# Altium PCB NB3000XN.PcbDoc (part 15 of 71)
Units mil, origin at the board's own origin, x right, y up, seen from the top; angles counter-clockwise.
Board outline 9527.56 x 6929.77 mil, 6 copper layers (Top Layer, GND+SHIELD, MidLayer1, MidLayer2, P2 - 3V3+5V0, Bottom Layer), stack 62.375 mil thick; 832 components, 1027 nets, 4655 pads, 4981 vias.
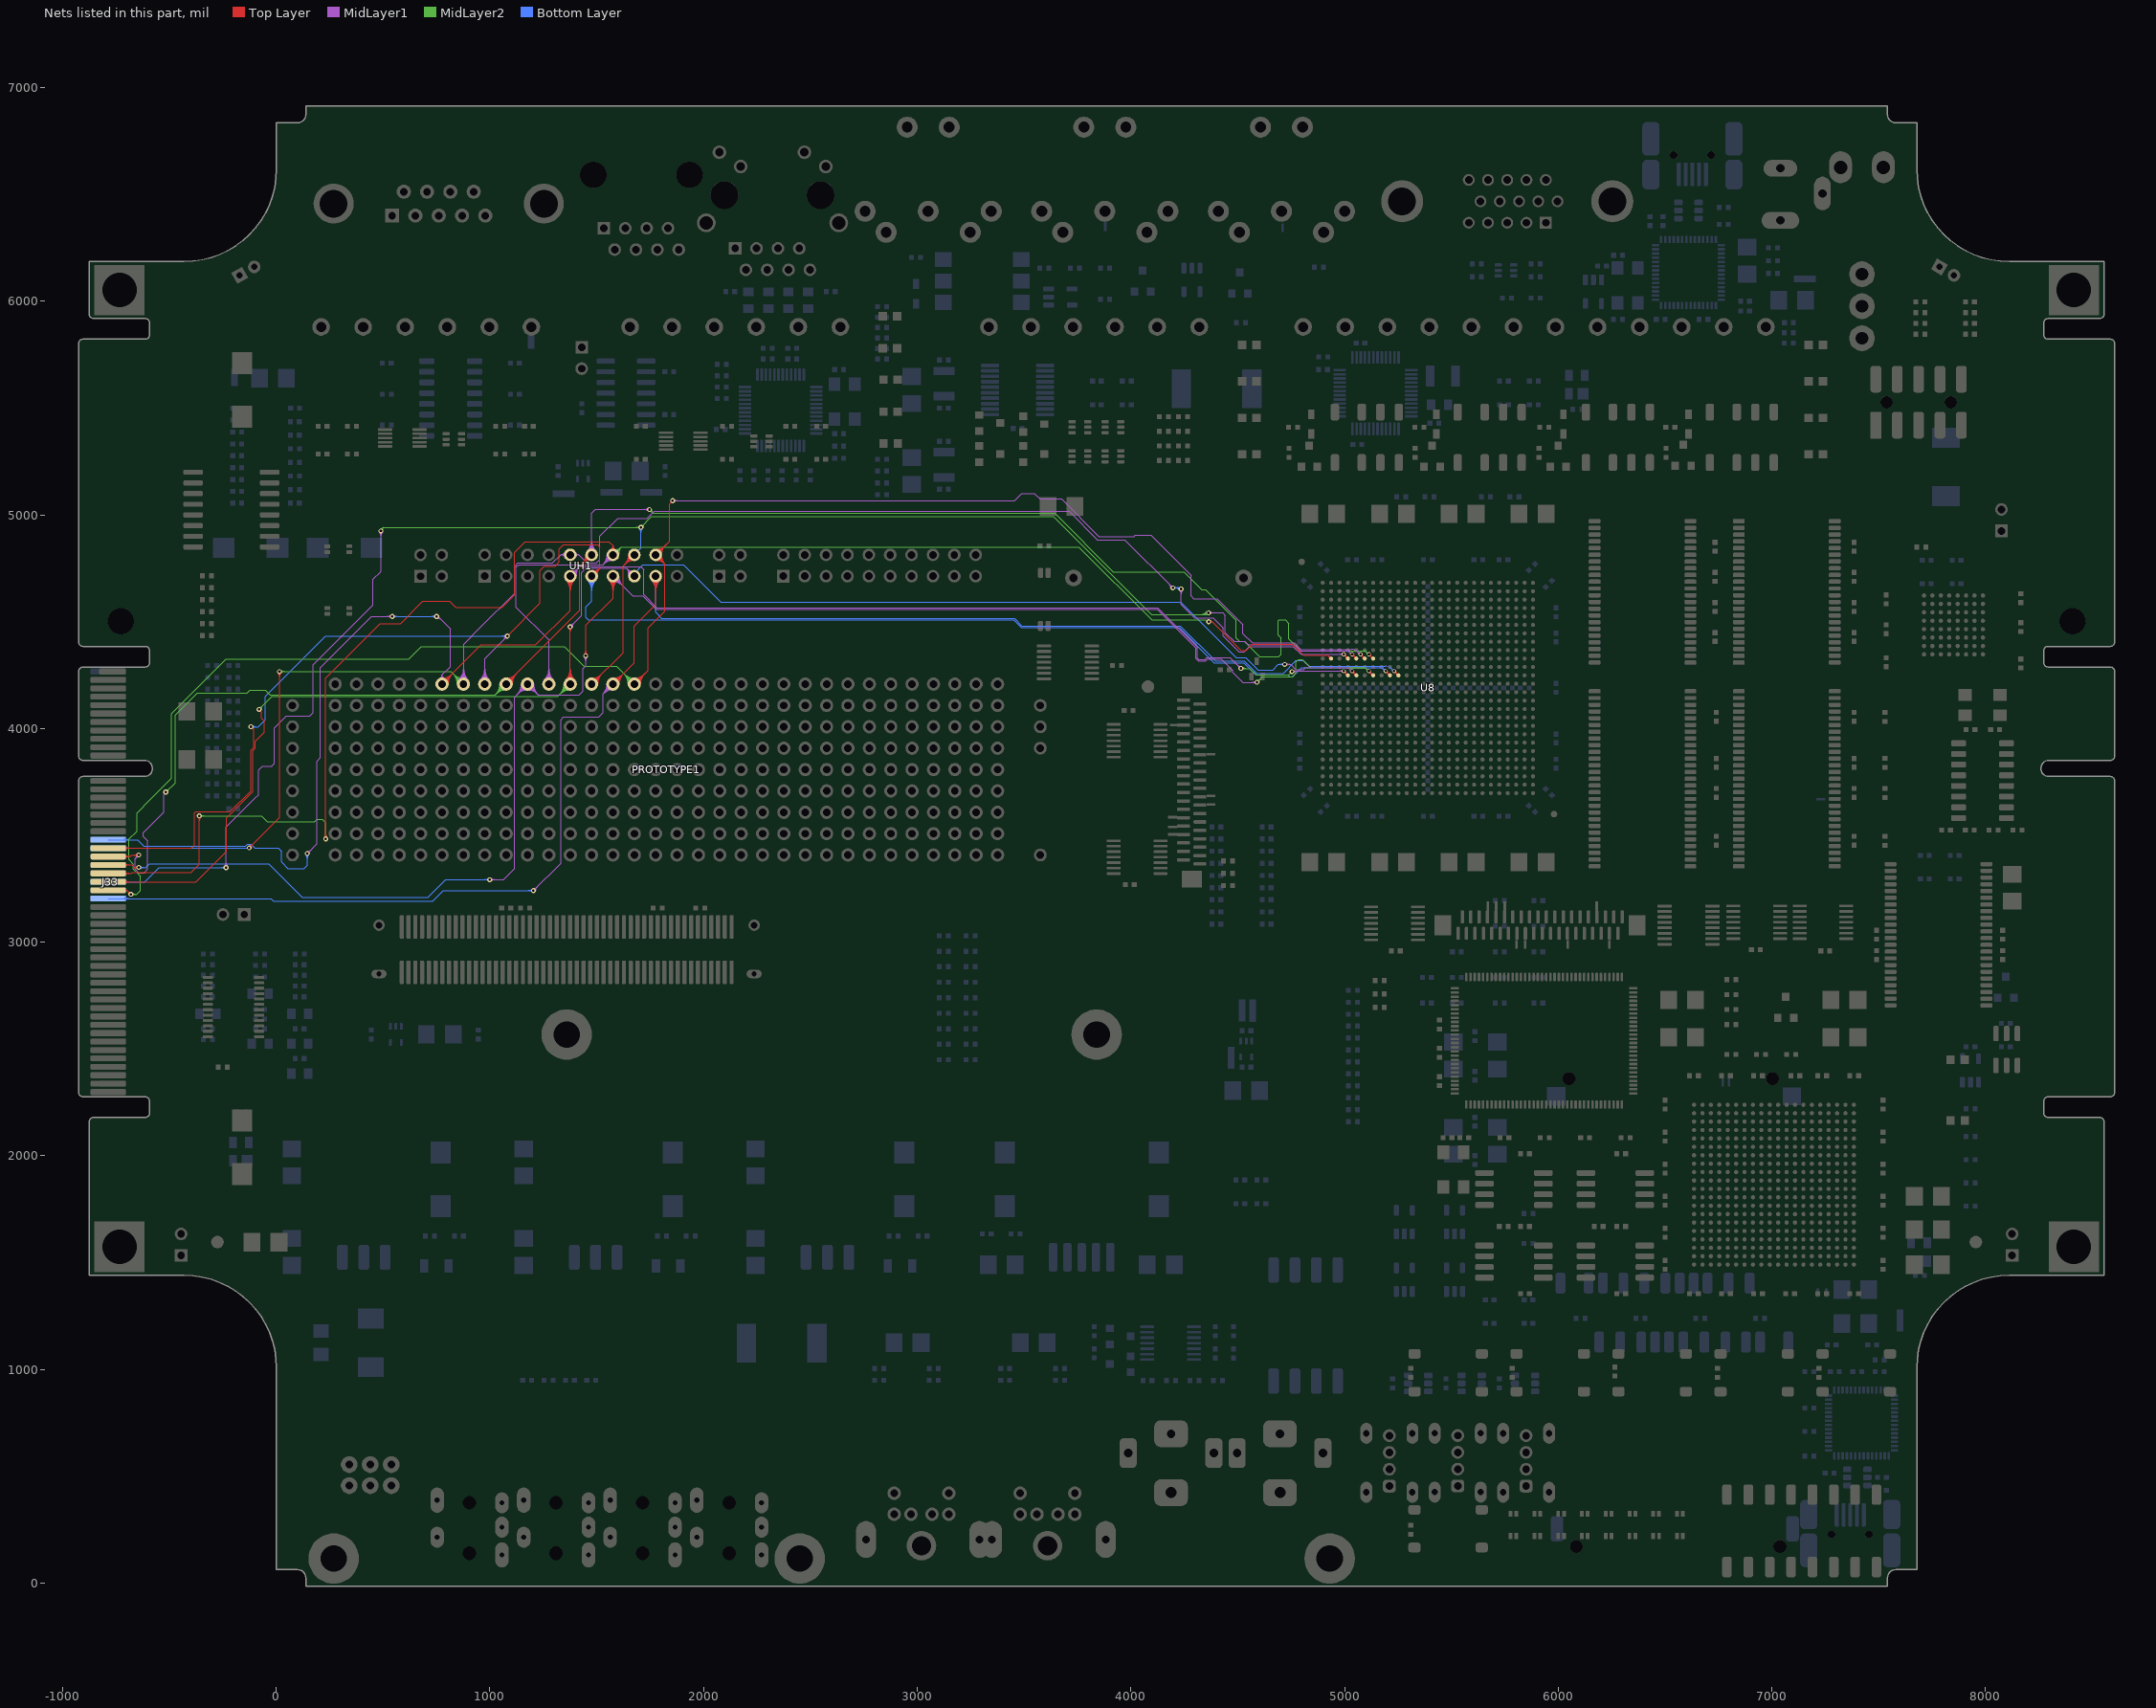
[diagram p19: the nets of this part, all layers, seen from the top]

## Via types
v1: diameter 23, hole 11.81, Top Layer to Bottom Layer, 3672 vias
v2: diameter 26, hole 11.81, Top Layer to Bottom Layer, 461 vias
v3: diameter 19, hole 11.81, Top Layer to Bottom Layer, tented both sides, 396 vias
v4: diameter 23.62, hole 11.81, Top Layer to Bottom Layer, 288 vias
v5: diameter 20, hole 11.81, Top Layer to Bottom Layer, 91 vias
v6: diameter 23, hole 11.81, Top Layer to Bottom Layer, tented both sides, 50 vias
v7: diameter 31, hole 11.81, Top Layer to Bottom Layer, 15 vias
v8: diameter 27.56, hole 11.81, Top Layer to Bottom Layer, tented both sides, 4 vias
v9: diameter 29, hole 11.81, Top Layer to Bottom Layer, 3 vias
v10: diameter 21, hole 11.81, Top Layer to Bottom Layer, 1 vias

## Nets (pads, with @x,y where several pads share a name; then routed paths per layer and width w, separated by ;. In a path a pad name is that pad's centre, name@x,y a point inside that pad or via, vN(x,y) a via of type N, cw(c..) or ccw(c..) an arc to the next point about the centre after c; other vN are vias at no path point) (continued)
ATE.UIO.IO7: J33.B19 PROTOTYPE1.H6 U8.M4 UH1.9 | length 9710.7
  Top Layer w4: PROTOTYPE1.H6@776.12,4208.23 959.59,4391.71 1215.19,4391.71 1376.12,4552.64 UH1.9@1376.12,4713.23 ; PROTOTYPE1.H6@776.12,4221.23 ccw(c776.12,4252.62) 798.31,4230.43 ccw(c820.51,4208.23) PROTOTYPE1.H6@789.12,4208.23 ; PROTOTYPE1.H6@776.12,4225.23 ccw(c776.12,4266.28) 805.14,4237.26 ccw(c834.16,4208.23) PROTOTYPE1.H6@793.12,4208.23 ; PROTOTYPE1.H6@776.12,4229.23 ccw(c776.12,4279.93) 811.97,4244.08 ccw(c847.82,4208.23) PROTOTYPE1.H6@797.12,4208.23 ; PROTOTYPE1.H6@776.12,4233.23 ccw(c776.12,4293.59) 818.8,4250.91 ccw(c861.48,4208.23) PROTOTYPE1.H6@801.12,4208.23 ; PROTOTYPE1.H6@776.12,4237.23 ccw(c776.12,4307.25) 825.63,4257.74 ccw(c875.13,4208.23) PROTOTYPE1.H6@805.12,4208.23 ; UH1.9@1356.66,4693.77 cw(c1309.66,4646.78) 1376.12,4646.78 cw(c1442.58,4646.78) UH1.9@1395.59,4693.77 ; UH1.9@1359.48,4696.6 cw(c1319.32,4656.43) 1376.12,4656.43 cw(c1432.92,4656.43) UH1.9@1392.76,4696.6 ; UH1.9@1362.31,4699.43 cw(c1328.98,4666.09) 1376.12,4666.09 cw(c1423.26,4666.09) UH1.9@1389.93,4699.43 ; UH1.9@1365.14,4702.26 cw(c1338.63,4675.75) 1376.12,4675.75 cw(c1413.61,4675.75) UH1.9@1387.1,4702.26 ; v3(4996.3,4268.74) U8.M4@5015.98,4249.06 ; U8.M4@5008.48,4249.06 ccw(c4990.38,4249.06) 5003.18,4261.86 ccw(c5015.98,4274.66) U8.M4@5015.98,4256.56 ; U8.M4@5008.64,4249.06 ccw(c4990.92,4249.06) 5003.45,4261.59 ccw(c5015.98,4274.12) U8.M4@5015.98,4256.4 ; 5009.1,4255.94 cw(c5021.91,4268.74) 5003.8,4268.74 ccw(c5021.91,4268.74) 5009.1,4255.94 ; 5009.1,4255.94 ccw(c4996.3,4243.13) 4996.3,4261.24 cw(c4996.3,4243.13) 5009.1,4255.94
  MidLayer1 w4: v1(145,3415) 190,3460 190,3846.87 206.19,3863.06 206.19,4285.08 446.15,4525.04 v1(542.86,4525.04) ; v1@145,3420.5 ccw(c145,3433.78) 154.39,3424.39 ccw(c163.78,3415) v1@150.5,3415 ; v1@145,3424.5 ccw(c145,3447.43) 161.22,3431.22 ccw(c177.43,3415) v1@154.5,3415 ; v1@536.14,4518.32 ccw(c519.92,4502.11) 519.92,4525.04 ccw(c519.92,4547.98) v1@536.14,4531.76 ; v1@538.97,4521.15 ccw(c529.58,4511.76) 529.58,4525.04 ccw(c529.58,4538.32) v1@538.97,4528.93 ; v1@750.86,4515.54 cw(c750.86,4478.92) 776.75,4504.82 ; v1@750.86,4519.54 cw(c750.86,4492.58) 769.92,4511.64 ; v1@750.86,4523.54 cw(c750.86,4506.24) 763.09,4518.47 cw(c769.61,4525.04) v1@760.36,4525.04 ; v1@756.52,4525.04 815.37,4466.19 815.37,4289.87 776.12,4250.62 ; PROTOTYPE1.H6@765.62,4235.27 ccw(c759.65,4250.62) 776.12,4250.62 ; PROTOTYPE1.H6@767.07,4231.54 ccw(c761.92,4244.77) 776.12,4244.77 ccw(c790.32,4244.77) PROTOTYPE1.H6@785.18,4231.54 ; PROTOTYPE1.H6@776.12,4208.23 776.12,4250.62 ; PROTOTYPE1.H6@786.63,4235.27 cw(c792.59,4250.62) 776.12,4250.62 ; UH1.9@1376.12,4713.23 1421.26,4758.37 ; UH1.9@1376.57,4728.76 ccw(c1377.55,4762.73) 1401.58,4738.7 ccw(c1425.61,4714.66) UH1.9@1391.64,4713.68 ; UH1.9@1376.69,4732.75 ccw(c1377.92,4775.48) 1408.14,4745.25 ccw(c1438.36,4715.03) UH1.9@1395.64,4713.8 ; UH1.9@1376.8,4736.75 ccw(c1378.29,4788.22) 1414.7,4751.81 ccw(c1451.11,4715.4) UH1.9@1399.64,4713.91 ; UH1.9@1376.92,4740.75 ccw(c1378.66,4800.97) 1421.26,4758.37 ; UH1.9@1403.64,4714.03 cw(c1463.86,4715.77) 1421.26,4758.37 ; v1@4505.69,4281.71 ccw(c4482.76,4281.71) 4498.97,4297.93 ccw(c4515.19,4314.14) v1@4515.19,4291.21 ; v1@4509.69,4281.71 ccw(c4496.41,4281.71) 4505.8,4291.1 ccw(c4515.19,4300.49) v1@4515.19,4287.21 ; v1(4515.19,4281.71) 4464.36,4332.54 4354.91,4332.54 4346.58,4324.21 4318.31,4324.21 4311.6,4330.92 4311.6,4380.77 4126.33,4566.04 1781.59,4566.04 1720,4627.63 1720,4745 1706.63,4758.37 1421.26,4758.37 ; v1(4754.19,4266.71) 4770.19,4266.71 ; v1@4762.53,4262.16 cw(c4770.19,4257.98) 4770.19,4266.71 ; v1@4762.53,4271.26 ccw(c4770.19,4275.43) 4770.19,4266.71 ; v3@4991,4263.44 ccw(c4978.19,4250.63) 4978.19,4268.74 ccw(c4978.19,4286.85) v3@4991,4274.04 ; v3@4991.11,4263.55 ccw(c4978.57,4251.01) 4978.57,4268.74 ccw(c4978.57,4286.47) v3@4991.11,4273.93 ; v3(4996.3,4268.74) 4918.62,4268.74 4870,4268.74 4860,4268.74 4855.26,4268.74 4772.22,4268.74 4770.19,4266.71
  MidLayer2 w4: v1(4515.19,4281.71) 4555.54,4281.71 4586.21,4251.04 4738.52,4251.04 v1(4754.19,4266.71) ; v1@4519.08,4277.82 cw(c4528.47,4268.43) 4528.47,4281.71 cw(c4528.47,4294.99) v1@4519.08,4285.6 ; v1@4521.91,4274.99 cw(c4538.13,4258.77) 4538.13,4281.71 cw(c4538.13,4304.64) v1@4521.91,4288.43
  Bottom Layer w4: J33.B19@-785.98,3479.63 -649.38,3479.63 -619.75,3450 -142.93,3450 -133.72,3459.21 -119.23,3459.21 -100.89,3440.87 -75.87,3440.87 9.13,3440.87 25,3425 25,3375 55,3345 130,3345 145,3360 v1(145,3415) ; J33.B19@-711.58,3474.13 cw(c-698.3,3460.85) -698.3,3479.63 cw(c-698.3,3498.41) J33.B19@-711.58,3485.13 ; J33.B19@-708.76,3471.3 cw(c-688.65,3451.19) -688.65,3479.63 cw(c-688.65,3508.07) J33.B19@-708.76,3487.96 ; v1@138.28,3408.28 cw(c122.06,3392.06) 145,3392.06 cw(c167.93,3392.06) v1@151.72,3408.28 ; v1@141.11,3411.11 cw(c131.72,3401.72) 145,3401.72 cw(c158.28,3401.72) v1@148.89,3411.11 ; v1(542.86,4525.04) v1(750.86,4525.04) ; v1@546.75,4521.15 cw(c556.14,4511.76) 556.14,4525.04 cw(c556.14,4538.32) v1@546.75,4528.93 ; v1@549.57,4518.32 cw(c565.79,4502.11) 565.79,4525.04 cw(c565.79,4547.98) v1@549.57,4531.76 ; v1@744.14,4518.32 ccw(c727.92,4502.11) 727.92,4525.04 ccw(c727.92,4547.98) v1@744.14,4531.76 ; v1@746.97,4521.15 ccw(c737.58,4511.76) 737.58,4525.04 ccw(c737.58,4538.32) v1@746.97,4528.93
ATE.UIO.IO8: J33.B20 PROTOTYPE1.H7 U8.K4 UH1.10 | length 9204.3
  Top Layer w4: v1(-126.48,3441.71) 15.19,3583.37 15.19,4228.33 v1(15.19,4266.71) ; v1@-126.48,3447.21 ccw(c-126.48,3460.49) -117.09,3451.1 ccw(c-107.7,3441.71) v1@-120.98,3441.71 ; v1@-126.48,3451.21 ccw(c-126.48,3474.14) -110.26,3457.93 ccw(c-94.04,3441.71) v1@-116.98,3441.71 ; v1@8.47,4259.99 cw(c-7.74,4243.77) 15.19,4243.77 cw(c38.13,4243.77) v1@21.91,4259.99 ; v1@11.3,4262.82 cw(c1.91,4253.43) 15.19,4253.43 cw(c28.47,4253.43) v1@19.08,4262.82 ; v3(4996.3,4347.48) U8.K4@5015.98,4327.8 ; U8.K4@5008.48,4327.8 ccw(c4990.38,4327.8) 5003.18,4340.6 ccw(c5015.98,4353.4) U8.K4@5015.98,4335.3 ; U8.K4@5008.64,4327.8 ccw(c4990.92,4327.8) 5003.45,4340.33 ccw(c5015.98,4352.86) U8.K4@5015.98,4335.14 ; 5009.1,4334.68 cw(c5021.91,4347.48) 5003.8,4347.48 ccw(c5021.91,4347.48) 5009.1,4334.68 ; 5009.1,4334.68 ccw(c4996.3,4321.87) 4996.3,4339.98 cw(c4996.3,4321.87) 5009.1,4334.68
  MidLayer1 w4: PROTOTYPE1.H7@855.62,4228.74 ccw(c802.78,4281.58) 877.5,4281.58 ; PROTOTYPE1.H7@858.44,4225.91 ccw(c812.44,4271.92) 877.5,4271.92 ; PROTOTYPE1.H7@861.27,4223.08 ccw(c822.09,4262.26) 877.5,4262.26 ; PROTOTYPE1.H7@864.1,4220.26 ccw(c831.75,4252.6) 877.5,4252.6 ; PROTOTYPE1.H7@866.93,4217.43 ccw(c841.41,4242.95) 877.5,4242.95 ; PROTOTYPE1.H7@876.12,4208.23 876.12,4210 877.5,4211.38 877.5,4395.68 956.86,4475.04 1115.19,4633.37 1115.19,4758.37 1131.86,4775.04 1293.66,4775.04 1331.86,4813.23 ; 877.5,4245.95 ccw(c913.83,4245.95) PROTOTYPE1.H7@888.14,4220.26 ; 877.5,4255.6 ccw(c923.49,4255.6) PROTOTYPE1.H7@890.97,4223.08 ; 877.5,4265.26 ccw(c933.15,4265.26) PROTOTYPE1.H7@893.8,4225.91 ; 877.5,4274.92 ccw(c942.8,4274.92) PROTOTYPE1.H7@896.63,4228.74 ; UH1.10@1351.43,4801.06 ccw(c1331.86,4791.41) 1331.86,4813.23 ; UH1.10@1351.43,4825.41 cw(c1331.86,4835.06) 1331.86,4813.23 ; UH1.10@1355.02,4802.83 ccw(c1338.29,4794.58) 1338.29,4813.23 ccw(c1338.29,4831.89) UH1.10@1355.02,4823.64 ; UH1.10@1358.61,4804.6 ccw(c1344.72,4797.76) 1344.72,4813.23 ccw(c1344.72,4828.71) UH1.10@1358.61,4821.87 ; UH1.10@1398.28,4805.32 cw(c1409.51,4801.3) 1409.51,4813.23 cw(c1409.51,4825.17) UH1.10@1398.28,4821.15 ; UH1.10@1402.04,4803.97 cw(c1415.19,4799.28) 1415.19,4813.23 ; UH1.10@1402.04,4822.5 ccw(c1415.19,4827.19) 1415.19,4813.23 ; v1@4187.02,4658.37 ccw(c4164.09,4658.37) 4180.31,4674.59 ccw(c4196.52,4690.81) v1@4196.52,4667.87 ; v1@4191.02,4658.37 ccw(c4177.75,4658.37) 4187.14,4667.76 ccw(c4196.52,4677.15) v1@4196.52,4663.87 ; v1(4196.52,4658.37) 3971.52,4883.37 3844,4883.37 3710.33,5017.04 1768.67,5017.04 1735,4983.37 1598.52,4983.37 1515.19,4900.04 1515.19,4791.71 1498.52,4775.04 1453.38,4775.04 1415.19,4813.23 ; v1@4228.81,4646.66 cw(c4212.59,4630.44) 4235.52,4630.44 cw(c4258.46,4630.44) v1@4242.24,4646.66 ; v1@4231.64,4649.49 cw(c4222.25,4640.1) 4235.52,4640.1 cw(c4248.8,4640.1) v1@4239.41,4649.49 ; v1(4235.52,4653.37) 4235.52,4579.71 4297.52,4517.71 4385.15,4517.71 4432.86,4470 4432.86,4434.04 4506.9,4360 4530,4360 4554.71,4384.71 4760,4384.71 4797.23,4347.48 4810.14,4347.48 4860,4347.48 4870,4347.48 4918.62,4347.48 v3(4996.3,4347.48) ; v3@4991.11,4342.29 ccw(c4978.57,4329.75) 4978.57,4347.48 ccw(c4978.57,4365.21) v3@4991.11,4352.67 ; 1331.86,4813.23 UH1.10@1376.12,4813.23 1415.19,4813.23 ; 4978.19,4347.48 cw(c4978.19,4329.37) 4991,4342.18 ccw(c4978.19,4329.37) 4978.19,4347.48 ; 4978.19,4347.48 ccw(c4978.19,4365.59) 4991,4352.78 cw(c4978.19,4365.59) 4978.19,4347.48
  MidLayer2 w4: v1(15.19,4266.71) 817.65,4266.71 PROTOTYPE1.H7@876.12,4208.23 ; v1@19.08,4262.82 cw(c28.47,4253.43) 28.47,4266.71 cw(c28.47,4279.99) v1@19.08,4270.6 ; v1@21.91,4259.99 cw(c38.13,4243.77) 38.13,4266.71 cw(c38.13,4289.64) v1@21.91,4273.43 ; PROTOTYPE1.H7@847.12,4208.23 ccw(c777.11,4208.23) 826.62,4257.74 ccw(c876.12,4307.25) PROTOTYPE1.H7@876.12,4237.23 ; PROTOTYPE1.H7@851.12,4208.23 ccw(c790.77,4208.23) 833.44,4250.91 ccw(c876.12,4293.59) PROTOTYPE1.H7@876.12,4233.23 ; PROTOTYPE1.H7@855.12,4208.23 ccw(c804.42,4208.23) 840.27,4244.08 ccw(c876.12,4279.93) PROTOTYPE1.H7@876.12,4229.23 ; PROTOTYPE1.H7@859.12,4208.23 ccw(c818.08,4208.23) 847.1,4237.26 ccw(c876.12,4266.28) PROTOTYPE1.H7@876.12,4225.23 ; PROTOTYPE1.H7@863.12,4208.23 ccw(c831.74,4208.23) 853.93,4230.43 ccw(c876.12,4252.62) PROTOTYPE1.H7@876.12,4221.23
  Bottom Layer w4: J33.B20@-785.98,3440.26 -155,3440.26 -153.56,3441.71 v1(-126.48,3441.71) ; J33.B20@-711.58,3434.76 cw(c-698.3,3421.48) -698.3,3440.26 cw(c-698.3,3459.04) J33.B20@-711.58,3445.76 ; J33.B20@-708.76,3431.93 cw(c-688.65,3411.82) -688.65,3440.26 cw(c-688.65,3468.7) J33.B20@-708.76,3448.59 ; v1(4196.52,4658.37) 4230.52,4658.37 v1(4235.52,4653.37) ; v1@4200.41,4654.49 cw(c4209.8,4645.1) 4209.8,4658.37 cw(c4209.8,4671.65) v1@4200.41,4662.26 ; v1@4200.52,4658.37 cw(c4200.52,4618.37) v1@4228.81,4646.66 ; v1@4203.24,4651.66 cw(c4219.46,4635.44) 4219.46,4658.37 cw(c4219.46,4681.31) v1@4203.24,4665.09 ; 4210.17,4658.37 cw(c4210.17,4628.03) v1@4231.64,4649.49 ; 4219.83,4658.37 cw(c4219.83,4637.68) v1@4234.46,4652.31 ; 4224.66,4658.37 ccw(c4224.66,4664.24) v1@4228.81,4660.09
ATE.UIO.IO9: J33.A20 PROTOTYPE1.H8 U8.M9 UH1.11 | length 9283.3
  Top Layer w4: J33.A20@-785.98,3440.26 -394.74,3440.26 -381.5,3453.5 -381.5,3605 -376.5,3610 -216.31,3610 -118,3708.31 -118,3898.31 -105,3911.31 -105,3995.23 v1(-118.14,4008.37) ; J33.A20@-711.58,3434.76 cw(c-698.3,3421.48) -698.3,3440.26 cw(c-698.3,3459.04) J33.A20@-711.58,3445.76 ; J33.A20@-708.76,3431.93 cw(c-688.65,3411.82) -688.65,3440.26 cw(c-688.65,3468.7) J33.A20@-708.76,3448.59 ; v1(1081.52,4433.04) 1235,4586.52 1235,4740 1255,4760 1305,4760 1325,4780 1325,4840 1345,4860 1505,4860 1515.19,4849.81 1515.19,4752.3 ; v1@1081.52,4438.54 ccw(c1081.52,4451.82) 1090.91,4442.43 ccw(c1100.3,4433.04) v1@1087.02,4433.04 ; v1@1081.52,4442.54 ccw(c1081.52,4465.48) 1097.74,4449.26 ccw(c1113.96,4433.04) v1@1091.02,4433.04 ; UH1.11@1476.12,4713.23 1515.19,4752.3 ; UH1.11@1478.27,4728.61 ccw(c1481.53,4751.9) 1498.16,4735.27 ccw(c1514.78,4718.65) UH1.11@1491.5,4715.39 ; UH1.11@1478.83,4732.57 ccw(c1482.93,4761.85) 1503.83,4740.95 ccw(c1524.74,4720.04) UH1.11@1495.46,4715.94 ; UH1.11@1479.38,4736.54 ccw(c1484.32,4771.81) 1509.51,4746.62 ccw(c1534.7,4721.44) UH1.11@1499.42,4716.5 ; UH1.11@1479.94,4740.5 ccw(c1485.72,4781.77) 1515.19,4752.3 ; UH1.11@1503.38,4717.05 cw(c1544.66,4722.83) 1515.19,4752.3 ; v3(5193.15,4268.74) U8.M9@5212.83,4249.06 ; U8.M9@5205.33,4249.06 ccw(c5187.23,4249.06) 5200.03,4261.86 ccw(c5212.83,4274.66) U8.M9@5212.83,4256.56 ; U8.M9@5205.49,4249.06 ccw(c5187.77,4249.06) 5200.3,4261.59 ccw(c5212.83,4274.12) U8.M9@5212.83,4256.4 ; 5205.95,4255.94 ccw(c5193.15,4243.13) 5193.15,4261.24 cw(c5193.15,4243.13) 5205.95,4255.94 ; 5205.95,4255.94 cw(c5218.76,4268.74) 5200.65,4268.74 ccw(c5218.76,4268.74) 5205.95,4255.94
  MidLayer1 w4: PROTOTYPE1.H8@955.62,4228.74 ccw(c906.11,4278.25) 976.12,4278.25 ccw(c1046.13,4278.25) PROTOTYPE1.H8@996.63,4228.74 ; PROTOTYPE1.H8@958.44,4225.91 ccw(c915.77,4268.59) 976.12,4268.59 ccw(c1036.48,4268.59) PROTOTYPE1.H8@993.8,4225.91 ; PROTOTYPE1.H8@961.27,4223.08 ccw(c925.42,4258.93) 976.12,4258.93 ccw(c1026.82,4258.93) PROTOTYPE1.H8@990.97,4223.08 ; PROTOTYPE1.H8@964.1,4220.26 ccw(c935.08,4249.28) 976.12,4249.28 ccw(c1017.16,4249.28) PROTOTYPE1.H8@988.14,4220.26 ; PROTOTYPE1.H8@966.93,4217.43 ccw(c944.74,4239.62) 976.12,4239.62 ccw(c1007.51,4239.62) PROTOTYPE1.H8@985.31,4217.43 ; PROTOTYPE1.H8@976.12,4208.23 976.12,4327.64 v1(1081.52,4433.04) ; v1@1072.02,4433.04 cw(c1049.09,4433.04) 1065.31,4416.82 cw(c1081.52,4400.61) v1@1081.52,4423.54 ; v1@1076.02,4433.04 cw(c1062.75,4433.04) 1072.14,4423.65 cw(c1081.52,4414.26) v1@1081.52,4427.54
  Bottom Layer w4: v1(-118.14,4008.37) -84.81,4008.37 -51.48,4041.71 -51.48,4150.04 231.52,4433.04 v1(1081.52,4433.04) ; v1@-114.25,4004.49 cw(c-104.86,3995.1) -104.86,4008.37 cw(c-104.86,4021.65) v1@-114.25,4012.26 ; v1@-111.43,4001.66 cw(c-95.21,3985.44) -95.21,4008.37 cw(c-95.21,4031.31) v1@-111.43,4015.09 ; v1@1074.81,4426.32 ccw(c1058.59,4410.11) 1058.59,4433.04 ccw(c1058.59,4455.98) v1@1074.81,4439.76 ; v1@1077.64,4429.15 ccw(c1068.25,4419.76) 1068.25,4433.04 ccw(c1068.25,4446.32) v1@1077.64,4436.93 ; UH1.11@1456.66,4693.77 cw(c1409.66,4646.78) 1476.12,4646.78 cw(c1542.58,4646.78) UH1.11@1495.59,4693.77 ; UH1.11@1459.48,4696.6 cw(c1419.32,4656.43) 1476.12,4656.43 cw(c1532.92,4656.43) UH1.11@1492.76,4696.6 ; UH1.11@1462.31,4699.43 cw(c1428.98,4666.09) 1476.12,4666.09 cw(c1523.26,4666.09) UH1.11@1489.93,4699.43 ; UH1.11@1465.14,4702.26 cw(c1438.63,4675.75) 1476.12,4675.75 cw(c1513.61,4675.75) UH1.11@1487.1,4702.26 ; UH1.11@1476.12,4713.23 1476.12,4596.12 1450,4570 1450,4520 1461.63,4508.37 3451.5,4508.37 3486.88,4473 4225.56,4473 4390.19,4308.37 4528.19,4308.37 4585.52,4251.04 4733.86,4251.04 4743.19,4241.71 4757.65,4241.71 4800.19,4284.25 4855.26,4284.25 4860,4284.25 4870,4284.25 5076.1,4284.25 5169.64,4284.25 cw(c5169.64,4270.2) 5179.57,4280.13 ; v3@5185.68,4268.09 ccw(c5167.64,4266.51) 5179.28,4280.38 ccw(c5190.92,4294.25) v3@5192.5,4276.21
ATE.UIO.IO10: J33.A21 PROTOTYPE1.H9 U8.K7 UH1.12 | length 9907.1
  Top Layer w4: J33.A21@-785.98,3400.89 -685,3400.89 -677.52,3408.37 v1(-643.14,3408.37) ; J33.A21@-711.58,3395.39 cw(c-698.3,3382.11) -698.3,3400.89 cw(c-698.3,3419.67) J33.A21@-711.58,3406.39 ; J33.A21@-708.76,3392.56 cw(c-688.65,3372.45) -688.65,3400.89 cw(c-688.65,3429.33) J33.A21@-708.76,3409.22 ; v1@-649.86,3401.66 ccw(c-666.08,3385.44) -666.08,3408.37 ccw(c-666.08,3431.31) v1@-649.86,3415.09 ; v1@-647.03,3404.49 ccw(c-656.42,3395.1) -656.42,3408.37 ccw(c-656.42,3421.65) v1@-647.03,3412.26 ; PROTOTYPE1.H9@1076.12,4208.23 1420.73,4552.84 1420.73,4757.84 UH1.12@1476.12,4813.23 ; PROTOTYPE1.H9@1076.12,4221.23 ccw(c1076.12,4252.62) 1098.31,4230.43 ccw(c1120.51,4208.23) PROTOTYPE1.H9@1089.12,4208.23 ; PROTOTYPE1.H9@1076.12,4225.23 ccw(c1076.12,4266.28) 1105.14,4237.26 ccw(c1134.16,4208.23) PROTOTYPE1.H9@1093.12,4208.23 ; PROTOTYPE1.H9@1076.12,4229.23 ccw(c1076.12,4279.93) 1111.97,4244.08 ccw(c1147.82,4208.23) PROTOTYPE1.H9@1097.12,4208.23 ; PROTOTYPE1.H9@1076.12,4233.23 ccw(c1076.12,4293.59) 1118.8,4250.91 ccw(c1161.48,4208.23) PROTOTYPE1.H9@1101.12,4208.23 ; PROTOTYPE1.H9@1076.12,4237.23 ccw(c1076.12,4307.25) 1125.63,4257.74 ccw(c1175.13,4208.23) PROTOTYPE1.H9@1105.12,4208.23 ; UH1.12@1448.59,4813.23 cw(c1382.14,4813.23) 1429.13,4766.24 cw(c1476.12,4719.25) UH1.12@1476.12,4785.71 ; UH1.12@1452.59,4813.23 cw(c1395.79,4813.23) 1435.96,4773.07 cw(c1476.12,4732.91) UH1.12@1476.12,4789.71 ; UH1.12@1456.59,4813.23 cw(c1409.45,4813.23) 1442.79,4779.9 cw(c1476.12,4746.56) UH1.12@1476.12,4793.71 ; UH1.12@1460.59,4813.23 cw(c1423.11,4813.23) 1449.61,4786.73 cw(c1476.12,4760.22) UH1.12@1476.12,4797.71 ; v3(5114.41,4347.48) U8.K7@5134.09,4327.8 ; U8.K7@5126.59,4327.8 ccw(c5108.49,4327.8) 5121.29,4340.6 ccw(c5134.09,4353.4) U8.K7@5134.09,4335.3 ; U8.K7@5126.75,4327.8 ccw(c5109.03,4327.8) 5121.56,4340.33 ccw(c5134.09,4352.86) U8.K7@5134.09,4335.14 ; 5127.21,4334.68 ccw(c5114.41,4321.87) 5114.41,4339.98 cw(c5114.41,4321.87) 5127.21,4334.68 ; 5127.21,4334.68 cw(c5140.02,4347.48) 5121.91,4347.48 ccw(c5140.02,4347.48) 5127.21,4334.68
  MidLayer1 w4: v1@-652.64,3408.37 cw(c-675.58,3408.37) -659.36,3392.16 cw(c-643.14,3375.94) v1@-643.14,3398.87 ; v1@-648.64,3408.37 cw(c-661.92,3408.37) -652.53,3398.99 cw(c-643.14,3389.6) v1@-643.14,3402.87 ; v1(-643.14,3408.37) -661.14,3390.37 -661.14,3341.71 -644.48,3325.04 -618.14,3325.04 -601.48,3341.71 -601.48,3473.71 -621.41,3493.64 -621.41,3513.59 -526.48,3608.52 -526.48,3693.04 v1(-516.81,3702.71) ; UH1.12@1456.66,4832.7 ccw(c1409.66,4879.69) 1476.12,4879.69 ccw(c1542.58,4879.69) UH1.12@1495.59,4832.7 ; UH1.12@1459.48,4829.87 ccw(c1419.32,4870.04) 1476.12,4870.04 ccw(c1532.92,4870.04) UH1.12@1492.76,4829.87 ; UH1.12@1462.31,4827.04 ccw(c1428.98,4860.38) 1476.12,4860.38 ccw(c1523.26,4860.38) UH1.12@1489.93,4827.04 ; UH1.12@1465.14,4824.21 ccw(c1438.63,4850.72) 1476.12,4850.72 ccw(c1513.61,4850.72) UH1.12@1487.1,4824.21 ; UH1.12@1476.12,4813.23 1476.12,5008.37 1493.12,5025.37 v1(1746.86,5025.37) ; v1@1740.14,5018.66 ccw(c1723.92,5002.44) 1723.92,5025.37 ccw(c1723.92,5048.31) v1@1740.14,5032.09 ; v1@1742.97,5021.49 ccw(c1733.58,5012.1) 1733.58,5025.37 ccw(c1733.58,5038.65) v1@1742.97,5029.26
  MidLayer2 w4: v1(-516.81,3702.71) -473,3746.52 -473,4063.71 -370,4166.71 -135,4166.71 -121.71,4180 -50,4180 -28.04,4158.04 1025.93,4158.04 PROTOTYPE1.H9@1076.12,4208.23 ; v1@-516.81,3708.21 ccw(c-516.81,3721.49) -507.42,3712.1 ccw(c-498.03,3702.71) v1@-511.31,3702.71 ; v1@-516.81,3712.21 ccw(c-516.81,3735.14) -500.59,3718.93 ccw(c-484.37,3702.71) v1@-507.31,3702.71 ; PROTOTYPE1.H9@1047.12,4208.23 cw(c977.11,4208.23) 1026.62,4158.73 cw(c1076.12,4109.22) PROTOTYPE1.H9@1076.12,4179.23 ; PROTOTYPE1.H9@1051.12,4208.23 cw(c990.77,4208.23) 1033.44,4165.56 cw(c1076.12,4122.88) PROTOTYPE1.H9@1076.12,4183.23 ; PROTOTYPE1.H9@1055.12,4208.23 cw(c1004.42,4208.23) 1040.27,4172.39 cw(c1076.12,4136.54) PROTOTYPE1.H9@1076.12,4187.23 ; PROTOTYPE1.H9@1059.12,4208.23 cw(c1018.08,4208.23) 1047.1,4179.21 cw(c1076.12,4150.19) PROTOTYPE1.H9@1076.12,4191.23 ; PROTOTYPE1.H9@1063.12,4208.23 cw(c1031.74,4208.23) 1053.93,4186.04 cw(c1076.12,4163.85) PROTOTYPE1.H9@1076.12,4195.23 ; v1@1746.86,5015.87 cw(c1746.86,4992.94) 1763.07,5009.16 cw(c1779.29,5025.37) v1@1756.36,5025.37 ; v1@1746.86,5019.87 cw(c1746.86,5006.6) 1756.25,5015.99 cw(c1765.64,5025.37) v1@1752.36,5025.37 ; v1(1746.86,5025.37) 1763.86,5008.37 3643.17,5008.37 3918.17,4733.37 4247.86,4733.37 4331.19,4650.04 4348.52,4650.04 4491.86,4506.71 4491.86,4423.37 4507.86,4407.37 4531.52,4407.37 4602.52,4336.37 4692.19,4336.37 4703.52,4347.71 4703.52,4423.71 4690.19,4437.04 4690.19,4504.37 4694.19,4508.37 4723.52,4508.37 4740.19,4491.71 4740.19,4419.69 4796.89,4362.99 4855.26,4362.99 4860,4362.99 4870,4362.99 4997.36,4362.99 5090.9,4362.99 cw(c5090.9,4348.94) 5100.83,4358.87 ; v3@5106.94,4346.83 ccw(c5088.9,4345.25) 5100.54,4359.12 ccw(c5112.18,4372.99) v3@5113.76,4354.95
ATE.UIO.IO11: J33.A22 PROTOTYPE1.H10 U8.M7 UH1.13 | length 9806.1
  Top Layer w4: J33.A22@-785.98,3361.52 -675,3361.52 -663.52,3350.04 ; J33.A22@-711.58,3356.02 cw(c-698.3,3342.74) -698.3,3361.52 ; J33.A22@-711.58,3367.02 ccw(c-698.3,3380.31) -698.3,3361.52 ; J33.A22@-708.76,3353.19 cw(c-688.65,3333.09) -688.65,3361.52 cw(c-688.64,3389.96) J33.A22@-708.76,3369.85 ; v1@-650.42,3343.93 ccw(c-663.52,3332.94) -663.52,3350.04 ; v1@-650.42,3356.15 cw(c-663.52,3367.14) -663.52,3350.04 ; v1@-647.36,3346.51 ccw(c-654.94,3340.14) -654.94,3350.04 ccw(c-654.94,3359.94) v1@-647.36,3353.58 ; v1(-643.14,3350.04) -663.52,3350.04 ; v1@1441.81,4347.43 ccw(c1425.59,4363.64) 1448.52,4363.64 ccw(c1471.46,4363.64) v1@1455.24,4347.43 ; v1@1444.64,4344.6 ccw(c1435.25,4353.99) 1448.52,4353.99 ccw(c1461.8,4353.99) v1@1452.41,4344.6 ; v1(1448.52,4340.71) 1448.52,4483.37 1576.12,4610.97 UH1.13@1576.12,4713.23 ; UH1.13@1556.66,4693.77 cw(c1509.66,4646.78) 1576.12,4646.78 cw(c1642.58,4646.78) UH1.13@1595.59,4693.77 ; UH1.13@1559.48,4696.6 cw(c1519.32,4656.43) 1576.12,4656.43 cw(c1632.92,4656.43) UH1.13@1592.76,4696.6 ; UH1.13@1562.31,4699.43 cw(c1528.98,4666.09) 1576.12,4666.09 cw(c1623.26,4666.09) UH1.13@1589.93,4699.43 ; UH1.13@1565.14,4702.26 cw(c1538.63,4675.75) 1576.12,4675.75 cw(c1613.61,4675.75) UH1.13@1587.1,4702.26 ; v3(5114.41,4268.74) U8.M7@5134.09,4249.06 ; U8.M7@5126.59,4249.06 ccw(c5108.49,4249.06) 5121.29,4261.86 ccw(c5134.09,4274.66) U8.M7@5134.09,4256.56 ; U8.M7@5126.75,4249.06 ccw(c5109.03,4249.06) 5121.56,4261.59 ccw(c5134.09,4274.12) U8.M7@5134.09,4256.4 ; 5127.21,4255.94 ccw(c5114.41,4243.13) 5114.41,4261.24 cw(c5114.41,4243.13) 5127.21,4255.94 ; 5127.21,4255.94 cw(c5140.02,4268.74) 5121.91,4268.74 ccw(c5140.02,4268.74) 5127.21,4255.94
  MidLayer1 w4: v1(999.52,3292.71) 1063.21,3292.71 1115.19,3344.69 1115.19,4147.3 PROTOTYPE1.H10@1176.12,4208.23 1225.98,4158.37 1418.37,4158.37 1435,4175 1435,4281.48 1448.52,4295 v1(1448.52,4340.71) ; v1@1003.41,3288.82 cw(c1012.8,3279.43) 1012.8,3292.71 cw(c1012.8,3305.99) v1@1003.41,3296.6 ; v1@1006.24,3285.99 cw(c1022.46,3269.77) 1022.46,3292.71 cw(c1022.46,3315.64) v1@1006.24,3299.43 ; PROTOTYPE1.H10@1147.12,4208.23 cw(c1077.11,4208.23) 1126.62,4158.73 cw(c1176.12,4109.22) 1176.12,4179.23 cw(c1176.12,4109.22) 1225.63,4158.73 cw(c1275.13,4208.23) PROTOTYPE1.H10@1205.12,4208.23 ; PROTOTYPE1.H10@1151.12,4208.23 cw(c1090.77,4208.23) 1133.44,4165.56 cw(c1176.12,4122.88) 1176.12,4183.23 cw(c1176.12,4122.88) 1218.8,4165.56 cw(c1261.48,4208.23) PROTOTYPE1.H10@1201.12,4208.23 ; PROTOTYPE1.H10@1155.12,4208.23 cw(c1104.42,4208.23) 1140.27,4172.39 cw(c1176.12,4136.54) 1176.12,4187.23 cw(c1176.12,4136.54) 1211.97,4172.39 cw(c1247.82,4208.23) PROTOTYPE1.H10@1197.12,4208.23 ; PROTOTYPE1.H10@1159.12,4208.23 cw(c1118.08,4208.23) 1147.1,4179.21 cw(c1176.12,4150.19) 1176.12,4191.23 cw(c1176.12,4150.19) 1205.14,4179.21 cw(c1234.16,4208.23) PROTOTYPE1.H10@1193.12,4208.23 ; PROTOTYPE1.H10@1163.12,4208.23 cw(c1131.74,4208.23) 1153.93,4186.04 cw(c1176.12,4163.85) 1176.12,4195.23 cw(c1176.12,4163.85) 1198.31,4186.04 cw(c1220.51,4208.23) PROTOTYPE1.H10@1189.12,4208.23 ; v1@1441.81,4333.99 cw(c1425.59,4317.77) 1448.52,4317.77 cw(c1471.46,4317.77) v1@1455.24,4333.99 ; v1@1444.64,4336.82 cw(c1435.25,4327.43) 1448.52,4327.43 cw(c1461.8,4327.43) v1@1452.41,4336.82 ; UH1.13@1576.12,4685.71 cw(c1576.12,4619.25) 1623.11,4666.24 cw(c1670.11,4713.23) UH1.13@1603.65,4713.23 ; UH1.13@1576.12,4689.71 cw(c1576.12,4632.91) 1616.29,4673.07 cw(c1656.45,4713.23) UH1.13@1599.65,4713.23 ; UH1.13@1576.12,4693.71 cw(c1576.12,4646.56) 1609.46,4679.9 cw(c1642.79,4713.23) UH1.13@1595.65,4713.23 ; UH1.13@1576.12,4697.71 cw(c1576.12,4660.22) 1602.63,4686.73 cw(c1629.14,4713.23) UH1.13@1591.65,4713.23 ; UH1.13@1576.12,4713.23 1669.36,4620 1716.31,4620 1778.27,4558.04 4123.02,4558.04 4303.6,4377.45 4303.6,4327.6 4315,4316.21 4349.89,4316.21 4358.23,4324.54 4422.98,4324.54 4431.48,4316.04 4476.86,4270.66 4476.86,4263.37 4523.52,4216.71 v1(4590.19,4216.71) ; v1@4583.47,4209.99 ccw(c4567.26,4193.77) 4567.26,4216.71 ccw(c4567.26,4239.64) v1@4583.47,4223.43 ; v1@4586.3,4212.82 ccw(c4576.91,4203.43) 4576.91,4216.71 ccw(c4576.91,4229.99) v1@4586.3,4220.6
  MidLayer2 w4: v1(4590.19,4216.71) 4616.52,4243.04 4756.86,4243.04 4773.52,4259.71 4773.52,4311.04 4785.86,4323.37 4802.13,4323.37 4841.26,4284.25 4855.26,4284.25 4860,4284.25 4870,4284.25 4997.36,4284.25 5090.9,4284.25 cw(c5090.9,4270.2) 5100.83,4280.13 ; v1@4590.19,4222.21 ccw(c4590.19,4235.49) 4599.58,4226.1 ccw(c4608.97,4216.71) v1@4595.69,4216.71 ; v1@4590.19,4226.21 ccw(c4590.19,4249.14) 4606.41,4232.92 ccw(c4622.63,4216.71) v1@4599.69,4216.71 ; v3@5106.94,4268.09 ccw(c5088.9,4266.51) 5100.54,4280.38 ccw(c5112.18,4294.25) v3@5113.76,4276.21
  Bottom Layer w4: v1(-643.14,3350.04) -609.81,3350.04 -593.14,3366.71 -34.81,3366.71 121.9,3210 710,3210 792.71,3292.71 822.67,3292.71 v1(999.52,3292.71) ; v1@-639.25,3346.15 cw(c-629.86,3336.76) -629.86,3350.04 cw(c-629.86,3363.32) v1@-639.25,3353.93 ; v1@-636.43,3343.32 cw(c-620.21,3327.11) -620.21,3350.04 cw(c-620.21,3372.98) v1@-636.43,3356.76 ; v1@992.81,3285.99 ccw(c976.59,3269.77) 976.59,3292.71 ccw(c976.59,3315.64) v1@992.81,3299.43 ; v1@995.64,3288.82 ccw(c986.25,3279.43) 986.25,3292.71 ccw(c986.25,3305.99) v1@995.64,3296.6
ATE.UIO.IO12: J33.A23 PROTOTYPE1.H11 U8.K2 UH1.14 | length 10046.4
  Top Layer w4: J33.A23@-785.98,3322.15 -678.81,3322.15 -674.25,3326.71 -398.29,3326.71 -359.81,3365.19 v1(-359.81,3591.71) ; J33.A23@-711.58,3316.65 cw(c-698.3,3303.37) -698.3,3322.15 cw(c-698.3,3340.94) J33.A23@-711.58,3327.65 ; J33.A23@-708.76,3313.82 cw(c-688.65,3293.72) -688.65,3322.15 cw(c-688.64,3350.59) J33.A23@-708.76,3330.48 ; v1@-366.53,3584.99 cw(c-382.74,3568.77) -359.81,3568.77 cw(c-336.87,3568.77) v1@-353.09,3584.99 ; v1@-363.7,3587.82 cw(c-373.09,3578.43) -359.81,3578.43 cw(c-346.53,3578.43) v1@-355.92,3587.82 ; v1@225.14,3490.09 ccw(c208.92,3506.31) 231.86,3506.31 ccw(c254.79,3506.31) v1@238.57,3490.09 ; v1@227.97,3487.26 ccw(c218.58,3496.65) 231.86,3496.65 ccw(c245.14,3496.65) v1@235.75,3487.26 ; v1(231.86,3483.37) 231.86,4236.86 486.71,4491.71 581.86,4491.71 685.96,4595.81 811.69,4595.81 841.13,4566.37 1056.52,4566.37 1097.97,4607.82 1115.19,4625.04 1115.19,4825.04 1165.19,4875.04 1556.86,4875.04 1576.12,4855.78 ; UH1.14@1564.84,4838.35 ccw(c1557.01,4855.78) 1576.12,4855.78 ; UH1.14@1566.48,4834.7 ccw(c1559.79,4849.59) 1576.12,4849.59 ccw(c1592.45,4849.59) UH1.14@1585.76,4834.7 ; UH1.14@1568.12,4831.05 ccw(c1562.57,4843.41) 1576.12,4843.41 ccw(c1589.68,4843.41) UH1.14@1584.12,4831.05 ; UH1.14@1576.12,4813.23 1576.12,4855.78 ; UH1.14@1587.4,4838.35 cw(c1595.23,4855.78) 1576.12,4855.78 ; v1(4364.52,4500.04) 4381.86,4500.04 ; v1@4372.53,4494.93 cw(c4381.86,4488.98) 4381.86,4500.04 ; v1@4372.53,4505.15 ccw(c4381.86,4511.1) 4381.86,4500.04 ; 4856.86,4343.3 4855.26,4343.3 4860,4343.3 ; 4381.86,4500.04 4515.86,4366.04 4540,4366.04 4567.83,4393.87 4744,4393.87 4757.44,4393.87 4808.01,4343.3 4813.01,4343.3 4822,4343.3 4860,4343.3 ; 4860,4343.3 4870,4343.3 4917.53,4343.3 ; 4917.53,4343.3 cw(c4917.53,4333.15) 4924.71,4340.33 ; 4917.53,4343.3 cw(c4917.53,4333.15) 4924.71,4340.33 ; 4924.71,4340.33 ccw(c4937.24,4352.86) 4937.24,4335.14 cw(c4937.24,4352.86) 4924.71,4340.33 ; 4924.71,4340.33 cw(c4912.17,4327.8) 4929.9,4327.8 ccw(c4912.17,4327.8) 4924.71,4340.33
  MidLayer1 w4: PROTOTYPE1.H11@1255.62,4228.74 ccw(c1206.11,4278.25) 1276.12,4278.25 ccw(c1346.13,4278.25) PROTOTYPE1.H11@1296.63,4228.74 ; PROTOTYPE1.H11@1258.44,4225.91 ccw(c1215.77,4268.59) 1276.12,4268.59 ccw(c1336.48,4268.59) PROTOTYPE1.H11@1293.8,4225.91 ; PROTOTYPE1.H11@1261.27,4223.08 ccw(c1225.42,4258.93) 1276.12,4258.93 ccw(c1326.82,4258.93) PROTOTYPE1.H11@1290.97,4223.08 ; PROTOTYPE1.H11@1264.1,4220.26 ccw(c1235.08,4249.28) 1276.12,4249.28 ccw(c1317.16,4249.28) PROTOTYPE1.H11@1288.14,4220.26 ; PROTOTYPE1.H11@1266.93,4217.43 ccw(c1244.74,4239.62) 1276.12,4239.62 ccw(c1307.51,4239.62) PROTOTYPE1.H11@1285.31,4217.43 ; PROTOTYPE1.H11@1276.12,4208.23 1276.12,4415 1123.19,4567.93 1123.19,4755.06 1134.84,4766.71 1529.59,4766.71 ; UH1.14@1548.59,4813.04 cw(c1483.73,4812.58) 1529.6,4766.71 ; UH1.14@1552.59,4813.07 cw(c1497.15,4812.67) 1536.36,4773.47 cw(c1575.56,4734.27) UH1.14@1575.95,4789.71 ; UH1.14@1556.59,4813.1 cw(c1510.58,4812.77) 1543.12,4780.23 cw(c1575.66,4747.69) UH1.14@1575.98,4793.71 ; UH1.14@1560.59,4813.12 cw(c1524.01,4812.86) 1549.88,4786.99 cw(c1575.75,4761.12) UH1.14@1576.01,4797.71 ; UH1.14@1575.93,4785.71 ccw(c1575.46,4720.84) 1529.6,4766.71 ; UH1.14@1576.12,4813.23 1529.59,4766.71
  MidLayer2 w4: v1(-359.81,3591.71) -68.14,3591.71 -41.44,3565 180.15,3565 190.19,3575.04 216.52,3575.04 231.86,3559.71 v1(231.86,3483.37) ; v1@-355.92,3587.82 cw(c-346.53,3578.43) -346.53,3591.71 cw(c-346.53,3604.99) v1@-355.92,3595.6 ; v1@-353.09,3584.99 cw(c-336.87,3568.77) -336.87,3591.71 cw(c-336.87,3614.64) v1@-353.09,3598.43 ; v1@225.14,3490.09 ccw(c208.92,3506.31) 231.86,3506.31 ccw(c254.79,3506.31) v1@238.57,3490.09 ; v1@227.97,3487.26 ccw(c218.58,3496.65) 231.86,3496.65 ccw(c245.14,3496.65) v1@235.75,3487.26 ; UH1.14@1576.12,4813.23 1598.52,4813.24 1598.52,4833.37 1615.19,4850.04 ; UH1.14@1579.35,4828.42 ccw(c1583.94,4850.03) 1599.56,4834.41 ; UH1.14@1580.18,4832.34 ccw(c1585.77,4858.62) 1604.77,4839.62 ; UH1.14@1581.01,4836.25 ccw(c1587.59,4867.22) 1609.98,4844.83 ; UH1.14@1581.84,4840.16 ccw(c1589.42,4875.81) 1615.19,4850.04 ; UH1.14@1595.52,4815.47 cw(c1623.15,4818.67) 1603.48,4838.33 ; UH1.14@1599.49,4815.93 cw(c1633.64,4819.88) 1609.34,4844.19 ; UH1.14@1603.47,4816.39 cw(c1644.14,4821.09) 1615.19,4850.04 ; v1(4364.52,4500.04) 4356.86,4500.04 4348.52,4508.37 4097.92,4508.37 3756.25,4850.04 1615.19,4850.04
ATE.UIO.IO13: J33.A24 PROTOTYPE1.H12 U8.M5 UH1.15 | length 8841.7
  Top Layer w4: J33.A24@-785.98,3282.78 -374.7,3282.78 -233.35,3424.13 -233.35,3581.65 -110,3705 -110,3895 -97,3908 -97,3940.48 -55,3982.48 -55,4034.93 -67.81,4047.74 -67.81,4077.81 v1(-80,4090) ; J33.A24@-711.58,3277.28 cw(c-698.3,3264) -698.3,3282.78 cw(c-698.3,3301.56) J33.A24@-711.58,3288.28 ; J33.A24@-708.76,3274.45 cw(c-688.65,3254.35) -688.65,3282.78 cw(c-688.65,3311.22) J33.A24@-708.76,3291.11 ; PROTOTYPE1.H12@1355.62,4228.74 ccw(c1306.11,4278.25) 1376.12,4278.25 ccw(c1446.13,4278.25) PROTOTYPE1.H12@1396.63,4228.74 ; PROTOTYPE1.H12@1358.44,4225.91 ccw(c1315.77,4268.59) 1376.12,4268.59 ccw(c1436.48,4268.59) PROTOTYPE1.H12@1393.8,4225.91 ; PROTOTYPE1.H12@1361.27,4223.08 ccw(c1325.42,4258.93) 1376.12,4258.93 ccw(c1426.82,4258.93) PROTOTYPE1.H12@1390.97,4223.08 ; PROTOTYPE1.H12@1364.1,4220.26 ccw(c1335.08,4249.28) 1376.12,4249.28 ccw(c1417.16,4249.28) PROTOTYPE1.H12@1388.14,4220.26 ; PROTOTYPE1.H12@1366.93,4217.43 ccw(c1344.74,4239.62) 1376.12,4239.62 ccw(c1407.51,4239.62) PROTOTYPE1.H12@1385.31,4217.43 ; v4@1369.18,4469.25 cw(c1352.44,4452.5) 1376.12,4452.5 cw(c1399.81,4452.5) v4@1383.06,4469.25 ; v4@1372.01,4472.08 cw(c1362.09,4462.16) 1376.12,4462.16 cw(c1390.15,4462.16) v4@1380.23,4472.08 ; PROTOTYPE1.H12@1376.12,4208.23 v4(1376.12,4476.19) ; v3(5035.67,4268.74) U8.M5@5055.35,4249.06 ; U8.M5@5047.85,4249.06 ccw(c5029.75,4249.06) 5042.55,4261.86 ccw(c5055.35,4274.66) U8.M5@5055.35,4256.56 ; U8.M5@5048.01,4249.06 ccw(c5030.29,4249.06) 5042.82,4261.59 ccw(c5055.35,4274.12) U8.M5@5055.35,4256.4 ; 5048.47,4255.94 ccw(c5035.67,4243.13) 5035.67,4261.24 cw(c5035.67,4243.13) 5048.47,4255.94 ; 5048.47,4255.94 cw(c5061.28,4268.74) 5043.17,4268.74 ccw(c5061.28,4268.74) 5048.47,4255.94
  MidLayer1 w4: v4(1376.12,4476.19) 1430,4530.06 1430,4730 1450.37,4750.37 1638.98,4750.37 ; v4@1376.12,4482 ccw(c1376.12,4496.03) 1386.04,4486.11 ccw(c1395.96,4476.19) v4@1381.93,4476.19 ; v4@1376.12,4486 ccw(c1376.12,4509.68) 1392.87,4492.93 ccw(c1409.62,4476.19) v4@1385.93,4476.19 ; UH1.15@1649.04,4718.17 ccw(c1613.29,4724.68) 1638.98,4750.37 ; UH1.15@1652.97,4717.45 ccw(c1622.42,4723.01) 1644.38,4744.98 ccw(c1666.34,4766.94) UH1.15@1671.91,4736.38 ; UH1.15@1656.91,4716.73 ccw(c1631.55,4721.35) 1649.78,4739.58 ccw(c1668.01,4757.81) UH1.15@1672.62,4732.45 ; UH1.15@1660.84,4716.02 ccw(c1640.68,4719.69) 1655.17,4734.18 ccw(c1669.67,4748.68) UH1.15@1673.34,4728.51 ; UH1.15@1671.19,4740.32 cw(c1664.68,4776.07) 1638.98,4750.37 ; UH1.15@1676.12,4713.23 1638.98,4750.37 ; v1(4720.19,4300.04) 4747.19,4300.04 4770.49,4276.74 4801.49,4276.74 4809.49,4276.74 4817,4284.25 4860,4284.25 4870,4284.25 4918.62,4284.25 5012.16,4284.25 cw(c5012.16,4270.2) 5022.09,4280.13 ; v1@4724.08,4296.15 cw(c4733.47,4286.76) 4733.47,4300.04 cw(c4733.47,4313.32) v1@4724.08,4303.93 ; v1@4726.91,4293.32 cw(c4743.13,4277.11) 4743.13,4300.04 cw(c4743.13,4322.98) v1@4726.91,4306.76 ; v3@5028.2,4268.09 ccw(c5010.16,4266.51) 5021.8,4280.38 ccw(c5033.44,4294.25) v3@5035.02,4276.21
  MidLayer2 w4: v1(-80,4090) -19.96,4150.04 1185,4150.04 1317.89,4150 PROTOTYPE1.H12@1376.12,4208.23 ; v1@-80,4095.5 ccw(c-80,4108.78) -70.61,4099.39 ccw(c-61.22,4090) v1@-74.5,4090 ; v1@-80,4099.5 ccw(c-80,4122.43) -63.78,4106.22 ccw(c-47.57,4090) v1@-70.5,4090 ; PROTOTYPE1.H12@1347.12,4208.23 cw(c1277.11,4208.23) 1326.62,4158.73 cw(c1376.12,4109.22) PROTOTYPE1.H12@1376.12,4179.23 ; PROTOTYPE1.H12@1351.12,4208.23 cw(c1290.77,4208.23) 1333.44,4165.56 cw(c1376.12,4122.88) PROTOTYPE1.H12@1376.12,4183.23 ; PROTOTYPE1.H12@1355.12,4208.23 cw(c1304.42,4208.23) 1340.27,4172.39 cw(c1376.12,4136.54) PROTOTYPE1.H12@1376.12,4187.23 ; PROTOTYPE1.H12@1359.12,4208.23 cw(c1318.08,4208.23) 1347.1,4179.21 cw(c1376.12,4150.19) PROTOTYPE1.H12@1376.12,4191.23 ; PROTOTYPE1.H12@1363.12,4208.23 cw(c1331.74,4208.23) 1353.93,4186.04 cw(c1376.12,4163.85) PROTOTYPE1.H12@1376.12,4195.23
  Bottom Layer w4: UH1.15@1676.12,4713.23 1676.12,4716.71 1690.19,4716.71 1690.19,4741.71 1715.19,4766.71 1906.86,4766.71 2081.86,4591.71 4233.19,4591.71 4491.86,4333.04 4537.48,4333.04 4595.48,4275.04 4665.19,4275.04 4690.19,4300.04 v1(4720.19,4300.04) ; v1@4713.47,4293.32 ccw(c4697.26,4277.11) 4697.26,4300.04 ccw(c4697.26,4322.98) v1@4713.47,4306.76 ; v1@4716.3,4296.15 ccw(c4706.91,4286.76) 4706.91,4300.04 ccw(c4706.91,4313.32) v1@4716.3,4303.93
ATE.UIO.IO14: J33.B24 PROTOTYPE1.H13 U8.K5 UH1.16 | length 9764.4
  Top Layer w4: PROTOTYPE1.H13@1476.12,4208.23 1623.52,4355.64 1623.52,4760.64 UH1.16@1676.12,4813.23 ; PROTOTYPE1.H13@1476.12,4221.23 ccw(c1476.12,4252.62) 1498.31,4230.43 ccw(c1520.51,4208.23) PROTOTYPE1.H13@1489.12,4208.23 ; PROTOTYPE1.H13@1476.12,4225.23 ccw(c1476.12,4266.28) 1505.14,4237.26 ccw(c1534.16,4208.23) PROTOTYPE1.H13@1493.12,4208.23 ; PROTOTYPE1.H13@1476.12,4229.23 ccw(c1476.12,4279.93) 1511.97,4244.08 ccw(c1547.82,4208.23) PROTOTYPE1.H13@1497.12,4208.23 ; PROTOTYPE1.H13@1476.12,4233.23 ccw(c1476.12,4293.59) 1518.8,4250.91 ccw(c1561.48,4208.23) PROTOTYPE1.H13@1501.12,4208.23 ; PROTOTYPE1.H13@1476.12,4237.23 ccw(c1476.12,4307.25) 1525.63,4257.74 ccw(c1575.13,4208.23) PROTOTYPE1.H13@1505.12,4208.23 ; UH1.16@1648.59,4813.23 cw(c1582.14,4813.23) 1629.13,4766.24 cw(c1676.12,4719.25) UH1.16@1676.12,4785.71 ; UH1.16@1652.59,4813.23 cw(c1595.79,4813.23) 1635.96,4773.07 cw(c1676.12,4732.91) UH1.16@1676.12,4789.71 ; UH1.16@1656.59,4813.23 cw(c1609.45,4813.23) 1642.79,4779.9 cw(c1676.12,4746.56) UH1.16@1676.12,4793.71 ; UH1.16@1660.59,4813.23 cw(c1623.11,4813.23) 1649.61,4786.73 cw(c1676.12,4760.22) UH1.16@1676.12,4797.71 ; v3(5035.67,4347.48) U8.K5@5055.35,4327.8 ; U8.K5@5047.85,4327.8 ccw(c5029.75,4327.8) 5042.55,4340.6 ccw(c5055.35,4353.4) U8.K5@5055.35,4335.3 ; U8.K5@5048.01,4327.8 ccw(c5030.29,4327.8) 5042.82,4340.33 ccw(c5055.35,4352.86) U8.K5@5055.35,4335.14 ; 5048.47,4334.68 ccw(c5035.67,4321.87) 5035.67,4339.98 cw(c5035.67,4321.87) 5048.47,4334.68 ; 5048.47,4334.68 cw(c5061.28,4347.48) 5043.17,4347.48 ccw(c5061.28,4347.48) 5048.47,4334.68
  MidLayer1 w4: v1@-241.53,3355.76 ccw(c-257.74,3371.98) -234.81,3371.98 ccw(c-211.87,3371.98) v1@-228.09,3355.76 ; v1@-238.7,3352.93 ccw(c-248.09,3362.32) -234.81,3362.32 ccw(c-221.53,3362.32) v1@-230.92,3352.93 ; v1(-234.81,3349.04) -234.81,3538.88 -96.46,3677.22 -83.3,3690.39 -83.3,3805 -63.59,3824.71 -20,3824.71 -19.83,3824.87 ; -20,3825.04 -7.5,3837.54 -7.5,4002.35 48.52,4058.37 156.86,4058.37 173.52,4075.04 173.52,4297.67 453.97,4578.12 453.97,4699.49 490,4735.52 v1(490,4925) ; v1@483.28,4918.28 cw(c467.06,4902.06) 490,4902.06 cw(c512.93,4902.06) v1@496.72,4918.28 ; v1@486.11,4921.11 cw(c476.72,4911.72) 490,4911.72 cw(c503.28,4911.72) v1@493.89,4921.11 ; v1(4363.52,4541.71) 4429.15,4541.71 4440.86,4530 4440.86,4449.37 4482.86,4407.37 4533.86,4407.37 4548.52,4392.71 4763.31,4392.71 4793.03,4362.99 4815,4362.99 4860,4362.99 4870,4362.99 4918.62,4362.99 5012.16,4362.99 cw(c5012.16,4348.94) 5022.09,4358.87 ; v1@4367.41,4537.82 cw(c4376.8,4528.43) 4376.8,4541.71 cw(c4376.8,4554.99) v1@4367.41,4545.6 ; v1@4370.24,4534.99 cw(c4386.46,4518.77) 4386.46,4541.71 cw(c4386.46,4564.64) v1@4370.24,4548.43 ; v3@5028.2,4346.83 ccw(c5010.16,4345.25) 5021.8,4359.12 ccw(c5033.44,4372.99) v3@5035.02,4354.95
  MidLayer2 w4: v1(490,4925) 490,4931.85 499.86,4941.71 ; v1@490,4934.5 ccw(c490,4940.9) 494.52,4936.37 ; v1@494.78,4927.73 cw(c502.19,4931.96) 496.15,4938 ; v1@498.25,4929.71 cw(c506.91,4934.66) 499.86,4941.71 ; v1@1700.14,4934.99 ccw(c1683.92,4918.77) 1683.92,4941.71 ccw(c1683.92,4964.64) v1@1700.14,4948.43 ; v1@1702.97,4937.82 ccw(c1693.58,4928.43) 1693.58,4941.71 ccw(c1693.58,4954.99) v1@1702.97,4945.6 ; v1@1706.86,4947.21 ccw(c1706.86,4960.49) 1716.25,4951.1 ccw(c1725.64,4941.71) v1@1712.36,4941.71 ; v1@1706.86,4951.21 ccw(c1706.86,4974.14) 1723.07,4957.93 ccw(c1739.29,4941.71) v1@1716.36,4941.71 ; 4320.47,4533.37 ccw(c4320.47,4584.76) v1@4356.81,4548.43 ; 4330.13,4533.37 ccw(c4330.13,4575.1) v1@4359.64,4545.6 ; 4339.79,4533.37 ccw(c4339.79,4565.45) v1@4362.46,4542.77 ; 4349.44,4533.37 ccw(c4349.44,4555.79) v1@4365.29,4539.94 ; v1(4363.52,4541.71) 4355.19,4533.37 4095.54,4533.37 3636.92,4992 1757.15,4992 v1(1706.86,4941.71) 499.86,4941.71
  Bottom Layer w4: J33.B24@-785.98,3282.78 -615,3282.78 -548.74,3349.04 v1(-234.81,3349.04) v1@-234.81,3348.71 ; J33.B24@-711.58,3277.28 cw(c-698.3,3264) -698.3,3282.78 cw(c-698.3,3301.56) J33.B24@-711.58,3288.28 ; J33.B24@-708.76,3274.45 cw(c-688.65,3254.35) -688.65,3282.78 cw(c-688.65,3311.22) J33.B24@-708.76,3291.11 ; v1@-241.53,3342.32 ccw(c-257.74,3326.11) -257.74,3349.04 ccw(c-257.74,3371.98) v1@-241.53,3355.76 ; v1@-238.7,3345.15 ccw(c-248.09,3335.76) -248.09,3349.04 ccw(c-248.09,3362.32) v1@-238.7,3352.93 ; UH1.16@1676.12,4813.23 1706.86,4843.97 v1(1706.86,4941.71) ; v1@1700.14,4934.99 cw(c1683.92,4918.77) 1706.86,4918.77 cw(c1729.79,4918.77) v1@1713.57,4934.99 ; v1@1702.97,4937.82 cw(c1693.58,4928.43) 1706.86,4928.43 cw(c1720.14,4928.43) v1@1710.75,4937.82
ATE.UIO.IO15: J33.B26 PROTOTYPE1.H14 U8.M10 UH1.17 | length 9310
  Top Layer w4: PROTOTYPE1.H14@1576.12,4208.23 1675,4307.11 1675,4480 1776.12,4581.12 UH1.17@1776.12,4713.23 ; PROTOTYPE1.H14@1576.12,4221.23 ccw(c1576.12,4252.62) 1598.31,4230.43 ccw(c1620.51,4208.23) PROTOTYPE1.H14@1589.12,4208.23 ; PROTOTYPE1.H14@1576.12,4225.23 ccw(c1576.12,4266.28) 1605.14,4237.26 ccw(c1634.16,4208.23) PROTOTYPE1.H14@1593.12,4208.23 ; PROTOTYPE1.H14@1576.12,4229.23 ccw(c1576.12,4279.93) 1611.97,4244.08 ccw(c1647.82,4208.23) PROTOTYPE1.H14@1597.12,4208.23 ; PROTOTYPE1.H14@1576.12,4233.23 ccw(c1576.12,4293.59) 1618.8,4250.91 ccw(c1661.48,4208.23) PROTOTYPE1.H14@1601.12,4208.23 ; PROTOTYPE1.H14@1576.12,4237.23 ccw(c1576.12,4307.25) 1625.63,4257.74 ccw(c1675.13,4208.23) PROTOTYPE1.H14@1605.12,4208.23 ; UH1.17@1756.66,4693.77 cw(c1709.66,4646.78) 1776.12,4646.78 cw(c1842.58,4646.78) UH1.17@1795.59,4693.77 ; UH1.17@1759.48,4696.6 cw(c1719.32,4656.43) 1776.12,4656.43 cw(c1832.92,4656.43) UH1.17@1792.76,4696.6 ; UH1.17@1762.31,4699.43 cw(c1728.98,4666.09) 1776.12,4666.09 cw(c1823.26,4666.09) UH1.17@1789.93,4699.43 ; UH1.17@1765.14,4702.26 cw(c1738.63,4675.75) 1776.12,4675.75 cw(c1813.61,4675.75) UH1.17@1787.1,4702.26 ; v3(5232.52,4268.74) U8.M10@5252.2,4249.06 ; U8.M10@5244.7,4249.06 ccw(c5226.6,4249.06) 5239.4,4261.86 ccw(c5252.2,4274.66) U8.M10@5252.2,4256.56 ; U8.M10@5244.86,4249.06 ccw(c5227.14,4249.06) 5239.67,4261.59 ccw(c5252.2,4274.12) U8.M10@5252.2,4256.4 ; 5245.32,4255.94 cw(c5258.13,4268.74) 5240.02,4268.74 ccw(c5258.13,4268.74) 5245.32,4255.94 ; 5245.32,4255.94 ccw(c5232.52,4243.13) 5232.52,4261.24 cw(c5232.52,4243.13) 5245.32,4255.94
  MidLayer1 w4: v1(1203.86,3241.71) 1331.86,3369.71 1331.86,4041.71 1345.15,4055 ; v1@1203.86,3247.21 ccw(c1203.86,3260.49) 1213.25,3251.1 ccw(c1222.64,3241.71) v1@1209.36,3241.71 ; v1@1203.86,3251.21 ccw(c1203.86,3274.14) 1220.07,3257.93 ccw(c1236.29,3241.71) v1@1213.36,3241.71 ; 1345,4055 1345.15,4055 ; PROTOTYPE1.H14@1547.16,4206.75 cw(c1488.39,4203.72) 1530,4162.12 ; PROTOTYPE1.H14@1551.15,4206.95 cw(c1500.49,4204.35) 1536.36,4168.48 cw(c1572.23,4132.61) PROTOTYPE1.H14@1574.84,4183.27 ; PROTOTYPE1.H14@1555.15,4207.16 cw(c1512.59,4204.97) 1542.72,4174.84 cw(c1572.86,4144.71) PROTOTYPE1.H14@1575.04,4187.26 ; PROTOTYPE1.H14@1559.14,4207.36 cw(c1524.69,4205.59) 1549.09,4181.2 cw(c1573.48,4156.81) PROTOTYPE1.H14@1575.25,4191.26 ; PROTOTYPE1.H14@1574.63,4179.27 ccw(c1571.61,4120.51) 1530,4162.12 ; PROTOTYPE1.H14@1576.12,4208.23 1530,4162.11 ; 1345.15,4055 1510,4055 1530,4075 1530,4162.11
  Bottom Layer w4: J33.B26@-785.98,3204.04 -24.23,3204.04 -12.38,3192.19 733.46,3192.19 782.98,3241.71 v1(1203.86,3241.71) ; J33.B26@-711.58,3198.54 cw(c-698.3,3185.26) -698.3,3204.04 cw(c-698.3,3222.82) J33.B26@-711.58,3209.54 ; J33.B26@-708.76,3195.71 cw(c-688.65,3175.6) -688.65,3204.04 cw(c-688.65,3232.48) J33.B26@-708.76,3212.37 ; v1@1197.14,3234.99 ccw(c1180.92,3218.77) 1180.92,3241.71 ccw(c1180.92,3264.64) v1@1197.14,3248.43 ; v1@1199.97,3237.82 ccw(c1190.58,3228.43) 1190.58,3241.71 ccw(c1190.58,3254.99) v1@1199.97,3245.6 ; UH1.17@1756.66,4693.77 cw(c1709.66,4646.78) 1776.12,4646.78 cw(c1842.58,4646.78) UH1.17@1795.59,4693.77 ; UH1.17@1759.48,4696.6 cw(c1719.32,4656.43) 1776.12,4656.43 cw(c1832.92,4656.43) UH1.17@1792.76,4696.6 ; UH1.17@1762.31,4699.43 cw(c1728.98,4666.09) 1776.12,4666.09 cw(c1823.26,4666.09) UH1.17@1789.93,4699.43 ; UH1.17@1765.14,4702.26 cw(c1738.63,4675.75) 1776.12,4675.75 cw(c1813.61,4675.75) UH1.17@1787.1,4702.26 ; UH1.17@1776.12,4713.23 1776.12,4543.88 1803.63,4516.37 3454.82,4516.37 3490.19,4481 4231.25,4481 4395.54,4316.71 4531.19,4316.71 4588.86,4259.04 4713.86,4259.04 4773.19,4318.37 4807.75,4318.37 4833.52,4292.6 4855.26,4292.6 4860,4292.6 4870,4292.6 5076.1,4292.6 5095.52,4292.6 5169.64,4292.6 5189.14,4292.6 cw(c5189.14,4250.87) 5218.65,4280.38 ; v3@5225.05,4268.09 ccw(c5207.01,4266.51) 5218.65,4280.38 ; v3@5231.87,4276.21 cw(c5230.29,4294.25) 5218.65,4280.38
ATE.UIO.IO16: J33.A25 PROTOTYPE1.H15 U8.K6 UH1.18 | length 9836.5
  Top Layer w4: J33.A25@-785.98,3243.41 -699.41,3243.41 ; J33.A25@-706.21,3238.88 cw(c-699.41,3236.05) -699.41,3243.41 ; J33.A25@-706.21,3247.94 ccw(c-699.41,3250.78) -699.41,3243.41 ; v1@-689.5,3224 ccw(c-712.44,3224) -696.22,3240.22 ccw(c-680,3256.43) v1@-680,3233.5 ; v1@-685.5,3224 ccw(c-698.78,3224) -689.39,3233.39 ccw(c-680,3242.78) v1@-680,3229.5 ; v1(-680,3224) -699.41,3243.41 ; PROTOTYPE1.H15@1676.12,4208.23 1740.19,4272.3 1740.19,4470 1820,4549.81 1820,4769.36 UH1.18@1776.12,4813.23 1840.19,4877.3 1840.19,5051.71 v1(1855.19,5066.71) ; PROTOTYPE1.H15@1676.12,4221.23 ccw(c1676.12,4252.62) 1698.31,4230.43 ccw(c1720.51,4208.23) PROTOTYPE1.H15@1689.12,4208.23 ; PROTOTYPE1.H15@1676.12,4225.23 ccw(c1676.12,4266.28) 1705.14,4237.26 ccw(c1734.16,4208.23) PROTOTYPE1.H15@1693.12,4208.23 ; PROTOTYPE1.H15@1676.12,4229.23 ccw(c1676.12,4279.93) 1711.97,4244.08 ccw(c1747.82,4208.23) PROTOTYPE1.H15@1697.12,4208.23 ; PROTOTYPE1.H15@1676.12,4233.23 ccw(c1676.12,4293.59) 1718.8,4250.91 ccw(c1761.48,4208.23) PROTOTYPE1.H15@1701.12,4208.23 ; PROTOTYPE1.H15@1676.12,4237.23 ccw(c1676.12,4307.25) 1725.63,4257.74 ccw(c1775.13,4208.23) PROTOTYPE1.H15@1705.12,4208.23 ; UH1.18@1776.12,4828.76 ccw(c1776.12,4866.25) 1802.63,4839.74 ccw(c1829.14,4813.23) UH1.18@1791.65,4813.23 ; UH1.18@1776.12,4832.76 ccw(c1776.12,4879.91) 1809.46,4846.57 ccw(c1842.79,4813.23) UH1.18@1795.65,4813.23 ; UH1.18@1776.12,4836.76 ccw(c1776.12,4893.56) 1816.29,4853.4 ccw(c1856.45,4813.23) UH1.18@1799.65,4813.23 ; UH1.18@1776.12,4840.76 ccw(c1776.12,4907.22) 1823.11,4860.23 ccw(c1870.11,4813.23) UH1.18@1803.65,4813.23 ; UH1.18@1776.89,4797.73 cw(c1778.47,4766.08) 1800.87,4788.49 cw(c1823.28,4810.89) UH1.18@1791.63,4812.46 ; UH1.18@1777.09,4793.73 cw(c1779.07,4753.93) 1807.25,4782.11 cw(c1835.42,4810.29) UH1.18@1795.62,4812.26 ; UH1.18@1777.29,4789.74 cw(c1779.67,4741.79) 1813.62,4775.73 cw(c1847.57,4809.68) UH1.18@1799.62,4812.07 ; UH1.18@1777.49,4785.74 cw(c1780.28,4729.64) 1820,4769.36 cw(c1859.72,4809.08) UH1.18@1803.61,4811.87 ; v3(5075.04,4347.48) U8.K6@5094.72,4327.8 ; U8.K6@5087.22,4327.8 ccw(c5069.12,4327.8) 5081.92,4340.6 ccw(c5094.72,4353.4) U8.K6@5094.72,4335.3 ; U8.K6@5087.38,4327.8 ccw(c5069.66,4327.8) 5082.19,4340.33 ccw(c5094.72,4352.86) U8.K6@5094.72,4335.14 ; 5087.84,4334.68 cw(c5100.65,4347.48) 5082.54,4347.48 ccw(c5100.65,4347.48) 5087.84,4334.68 ; 5087.84,4334.68 ccw(c5075.04,4321.87) 5075.04,4339.98 cw(c5075.04,4321.87) 5087.84,4334.68
  MidLayer1 w4: v1(1855.19,5066.71) 1855.36,5066.54 3456.5,5066.54 3490,5100.04 3548.52,5100.04 3573.52,5075.04 3674.96,5075.04 3850.29,4899.71 4015.29,4899.71 4020.58,4905 4093.56,4905 4281.86,4716.71 4281.86,4620 4293.98,4607.88 4301.01,4607.88 4301.84,4608.71 4402.58,4608.71 4524.5,4486.79 4524.5,4444.44 4568.23,4400.71 4766.63,4400.71 4795.99,4371.34 4808.91,4371.34 4918.62,4371.34 4938.04,4371.34 5012.16,4371.34 ; v1@1859.08,5062.82 cw(c1868.07,5053.83) 1868.07,5066.54 ; v1@1859.08,5070.6 ccw(c1868.87,5080.39) 1868.87,5066.54 ; v1@1861.91,5059.99 cw(c1877.72,5044.18) 1877.72,5066.54 ; v1@1861.91,5073.43 ccw(c1878.53,5090.05) 1878.53,5066.54 ; 4998.23,4371.34 5012.16,4371.34 ; v3@5067.57,4346.83 ccw(c5049.53,4345.25) 5061.17,4359.12 ; v3@5074.39,4354.95 cw(c5072.81,4372.99) 5061.17,4359.12 ; 5012.16,4371.34 5031.66,4371.34 cw(c5031.66,4329.61) 5061.17,4359.12
  MidLayer2 w4: v1(-680,3224) -652.52,3224 -634.81,3241.71 -634.81,3308.71 -668.14,3342.04 -668.14,3365 -689.5,3386.36 -689.5,3482.5 -652,3520 -652,3604.83 -588.12,3668.71 -532.28,3724.55 -489,3767.83 -489,4070.34 -234.29,4325.04 620.52,4325.04 678.86,4383.37 1348.52,4383.37 1439.72,4292.18 1592.18,4292.18 PROTOTYPE1.H15@1676.12,4208.23 ; v1@-676.11,3220.11 cw(c-666.72,3210.72) -666.72,3224 cw(c-666.72,3237.28) v1@-676.11,3227.89 ; v1@-673.28,3217.28 cw(c-657.07,3201.06) -657.07,3224 cw(c-657.07,3246.93) v1@-673.28,3230.72 ; PROTOTYPE1.H15@1647.12,4208.23 ccw(c1577.11,4208.23) 1626.62,4257.74 ccw(c1676.12,4307.25) PROTOTYPE1.H15@1676.12,4237.23 ; PROTOTYPE1.H15@1651.12,4208.23 ccw(c1590.77,4208.23) 1633.44,4250.91 ccw(c1676.12,4293.59) PROTOTYPE1.H15@1676.12,4233.23 ; PROTOTYPE1.H15@1655.12,4208.23 ccw(c1604.42,4208.23) 1640.27,4244.08 ccw(c1676.12,4279.93) PROTOTYPE1.H15@1676.12,4229.23 ; PROTOTYPE1.H15@1659.12,4208.23 ccw(c1618.08,4208.23) 1647.1,4237.26 ccw(c1676.12,4266.28) PROTOTYPE1.H15@1676.12,4225.23 ; PROTOTYPE1.H15@1663.12,4208.23 ccw(c1631.74,4208.23) 1653.93,4230.43 ccw(c1676.12,4252.62) PROTOTYPE1.H15@1676.12,4221.23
